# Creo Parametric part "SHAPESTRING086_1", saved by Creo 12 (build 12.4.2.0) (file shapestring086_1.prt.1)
Units: Custom; MM, KILOGRAM, SECS

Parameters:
  PTC_WM_ITERATION = "0"
  PTC_WM_VERSION = "-.0"
  PTC_WM_LIFECYCLE_STATE = "In Work"
  PTC_WM_LIFECYCLE = "MO_CADDocument"
  PTC_WM_CREATED_BY = "Maximilian Roepper (Z0017RMS: MO)"
  PTC_WM_CREATED_ON = "18-Sep-26 11:36:42 AM"
  PTC_WM_MODIFIED_BY = "Maximilian Roepper (Z0017RMS: MO)"
  PTC_WM_MODIFIED_ON = "18-Sep-26 11:36:46 AM"
  PDMLINKNUMBER = "PDM000071454932"
  PTC_WM_NAME = "shapestring086_1.prt"
  PTC_WM_NUMBER = "PDM000071454932"

Other parameters: WEIGHT, WEIGHT_FACTOR, WEIGHT_ADD, _MASS_TEMP, _DIFF_TEMP, MC_ERRORS, SUPPLIER

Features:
  1. coordinate system
  2. datum plane "PRT_YZ"
  3. datum plane "PRT_XY"
  4. datum plane "PRT_XZ"
  5. coordinate system
  6. datum axis
  7. datum axis
  8. datum axis
  9. coordinate system
  10. imported feature

Other named items: PRT, SIEMENS_MO, DRW_VIEW_ORG, PRT_X, PRT_Y, PRT_Z, CS0, ROUGH_GROB

Layers: 00_STD_CSYS-KSYS, 01_STD_PLANES-EBENEN, 02_STD_AXES-ACHSEN, 03_STD_CSYS-KSYS, 24_IMPORT_FEAT-IMPORT_KE, INTFCLR

Surfaces: 1 plane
